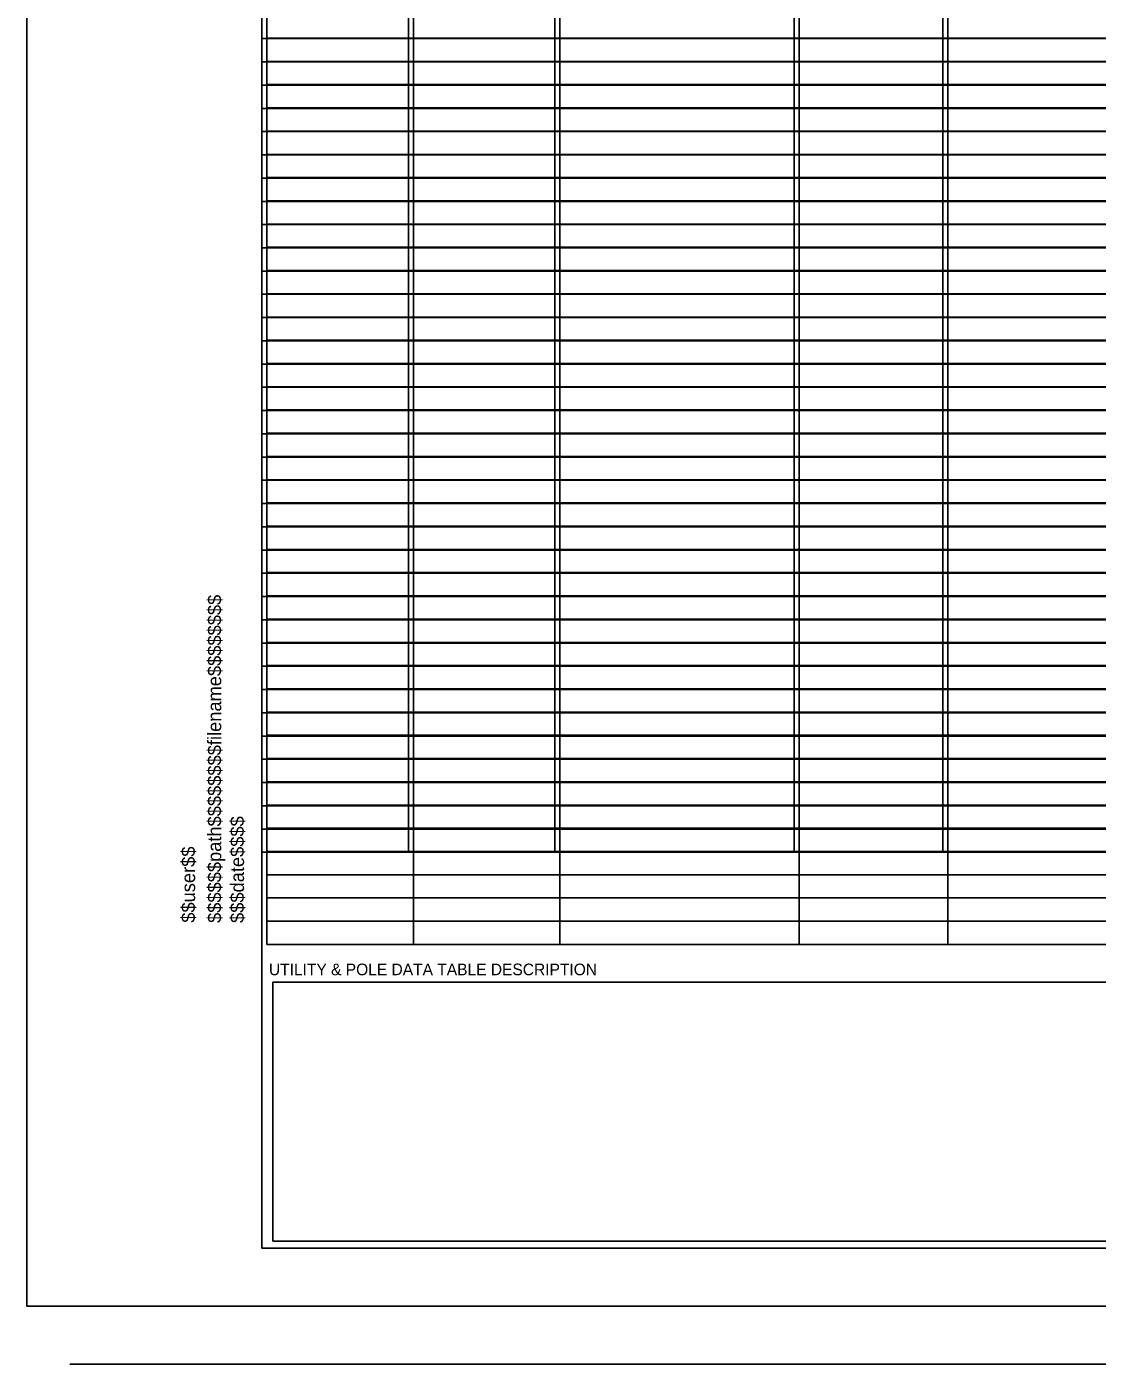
# Model space of a CAD drawing. Extents: x 11473 to 13269, y 16929 to 18079.
# Drawn here: x 11473 to 11933, y 16929 to 17505 of the extents above; entities that cross this region are included whole.
import ezdxf

# ---------------------------------------------------------------- set-up
doc = ezdxf.new("R2010")
doc.units = 0
for name, color, linetype in [('RD_SHT_Bndy', 7, 'Continuous'), ('RD_SHT_ID', 7, 'Continuous'), ('RD_SHT_Iplotshp', 7, 'Continuous'), ('RD_SHT_Misc2', 7, 'Continuous'), ('RD_SHT_Snap', 7, 'Continuous'), ('RD_SHT_TX', 7, 'Continuous')]:
    doc.layers.add(name, color=color, linetype=linetype)

msp = doc.modelspace()

# ---------------------------------------------------------------- linework, layer by layer
at = {"layer": 'RD_SHT_Bndy'}
for p, q in [((11573.83, 18029.35), (11573.83, 16979.35)), ((11573.83, 17129.35), (11573.83, 16979.4)), ((11573.83, 16979.35), (13248.83, 16979.35)), ((13251.23, 16954.35), (11491.23, 16954.35)), ((13251.23, 16929.35), (11491.23, 16929.35))]:
    msp.add_line(p, q, dxfattribs=at)
for points in [[(11573.83, 17499.8), (11636.83, 17499.8), (11636.83, 17509.81), (11573.83, 17509.81)], [(11636.83, 17499.8), (11699.83, 17499.8), (11699.83, 17509.81), (11636.83, 17509.81)], [(11699.83, 17499.8), (11802.84, 17499.8), (11802.84, 17509.81), (11699.83, 17509.81)], [(11802.84, 17499.8), (11866.84, 17499.8), (11866.84, 17509.81), (11802.84, 17509.81)], [(11866.84, 17499.8), (11973.81, 17499.8), (11973.81, 17509.81), (11866.84, 17509.81)], [(11573.83, 17489.8), (11636.83, 17489.8), (11636.83, 17499.8), (11573.83, 17499.8)], [(11636.83, 17489.8), (11699.83, 17489.8), (11699.83, 17499.8), (11636.83, 17499.8)], [(11699.83, 17489.8), (11802.84, 17489.8), (11802.84, 17499.8), (11699.83, 17499.8)], [(11802.84, 17489.8), (11866.84, 17489.8), (11866.84, 17499.8), (11802.84, 17499.8)], [(11866.84, 17489.8), (11973.81, 17489.8), (11973.81, 17499.8), (11866.84, 17499.8)], [(11573.83, 17479.8), (11636.83, 17479.8), (11636.83, 17489.8), (11573.83, 17489.8)], [(11636.83, 17479.8), (11699.83, 17479.8), (11699.83, 17489.8), (11636.83, 17489.8)], [(11699.83, 17479.8), (11802.84, 17479.8), (11802.84, 17489.8), (11699.83, 17489.8)], [(11802.84, 17479.8), (11866.84, 17479.8), (11866.84, 17489.8), (11802.84, 17489.8)], [(11866.84, 17479.8), (11973.81, 17479.8), (11973.81, 17489.8), (11866.84, 17489.8)], [(11573.83, 17469.79), (11636.83, 17469.79), (11636.83, 17479.8), (11573.83, 17479.8)], [(11636.83, 17469.79), (11699.83, 17469.79), (11699.83, 17479.8), (11636.83, 17479.8)], [(11699.83, 17469.79), (11802.84, 17469.79), (11802.84, 17479.8), (11699.83, 17479.8)], [(11802.84, 17469.79), (11866.84, 17469.79), (11866.84, 17479.8), (11802.84, 17479.8)], [(11866.84, 17469.79), (11973.81, 17469.79), (11973.81, 17479.8), (11866.84, 17479.8)], [(11573.83, 17459.79), (11636.83, 17459.79), (11636.83, 17469.79), (11573.83, 17469.79)], [(11636.83, 17459.79), (11699.83, 17459.79), (11699.83, 17469.79), (11636.83, 17469.79)], [(11699.83, 17459.79), (11802.84, 17459.79), (11802.84, 17469.79), (11699.83, 17469.79)], [(11802.84, 17459.79), (11866.84, 17459.79), (11866.84, 17469.79), (11802.84, 17469.79)], [(11866.84, 17459.79), (11973.81, 17459.79), (11973.81, 17469.79), (11866.84, 17469.79)], [(11573.83, 17449.78), (11636.83, 17449.78), (11636.83, 17459.79), (11573.83, 17459.79)], [(11636.83, 17449.78), (11699.83, 17449.78), (11699.83, 17459.79), (11636.83, 17459.79)], [(11699.83, 17449.78), (11802.84, 17449.78), (11802.84, 17459.79), (11699.83, 17459.79)], [(11802.84, 17449.78), (11866.84, 17449.78), (11866.84, 17459.79), (11802.84, 17459.79)], [(11866.84, 17449.78), (11973.81, 17449.78), (11973.81, 17459.79), (11866.84, 17459.79)], [(11573.83, 17439.78), (11636.83, 17439.78), (11636.83, 17449.78), (11573.83, 17449.78)], [(11636.83, 17439.78), (11699.83, 17439.78), (11699.83, 17449.78), (11636.83, 17449.78)], [(11699.83, 17439.78), (11802.84, 17439.78), (11802.84, 17449.78), (11699.83, 17449.78)], [(11802.84, 17439.78), (11866.84, 17439.78), (11866.84, 17449.78), (11802.84, 17449.78)], [(11866.84, 17439.78), (11973.81, 17439.78), (11973.81, 17449.78), (11866.84, 17449.78)], [(11573.83, 17429.77), (11636.83, 17429.77), (11636.83, 17439.78), (11573.83, 17439.78)], [(11636.83, 17429.77), (11699.83, 17429.77), (11699.83, 17439.78), (11636.83, 17439.78)], [(11699.83, 17429.77), (11802.84, 17429.77), (11802.84, 17439.78), (11699.83, 17439.78)], [(11802.84, 17429.77), (11866.84, 17429.77), (11866.84, 17439.78), (11802.84, 17439.78)], [(11866.84, 17429.77), (11973.81, 17429.77), (11973.81, 17439.78), (11866.84, 17439.78)], [(11573.83, 17419.77), (11636.83, 17419.77), (11636.83, 17429.77), (11573.83, 17429.77)], [(11636.83, 17419.77), (11699.83, 17419.77), (11699.83, 17429.77), (11636.83, 17429.77)], [(11699.83, 17419.77), (11802.84, 17419.77), (11802.84, 17429.77), (11699.83, 17429.77)], [(11802.84, 17419.77), (11866.84, 17419.77), (11866.84, 17429.77), (11802.84, 17429.77)], [(11866.84, 17419.77), (11973.81, 17419.77), (11973.81, 17429.77), (11866.84, 17429.77)], [(11573.83, 17409.77), (11636.83, 17409.77), (11636.83, 17419.77), (11573.83, 17419.77)], [(11636.83, 17409.77), (11699.83, 17409.77), (11699.83, 17419.77), (11636.83, 17419.77)], [(11699.83, 17409.77), (11802.84, 17409.77), (11802.84, 17419.77), (11699.83, 17419.77)], [(11802.84, 17409.77), (11866.84, 17409.77), (11866.84, 17419.77), (11802.84, 17419.77)], [(11866.84, 17409.77), (11973.81, 17409.77), (11973.81, 17419.77), (11866.84, 17419.77)], [(11573.83, 17399.76), (11636.83, 17399.76), (11636.83, 17409.77), (11573.83, 17409.77)], [(11636.83, 17399.76), (11699.83, 17399.76), (11699.83, 17409.77), (11636.83, 17409.77)], [(11699.83, 17399.76), (11802.84, 17399.76), (11802.84, 17409.77), (11699.83, 17409.77)], [(11802.84, 17399.76), (11866.84, 17399.76), (11866.84, 17409.77), (11802.84, 17409.77)], [(11866.84, 17399.76), (11973.81, 17399.76), (11973.81, 17409.77), (11866.84, 17409.77)], [(11573.83, 17389.76), (11636.83, 17389.76), (11636.83, 17399.76), (11573.83, 17399.76)], [(11636.83, 17389.76), (11699.83, 17389.76), (11699.83, 17399.76), (11636.83, 17399.76)], [(11699.83, 17389.76), (11802.84, 17389.76), (11802.84, 17399.76), (11699.83, 17399.76)], [(11802.84, 17389.76), (11866.84, 17389.76), (11866.84, 17399.76), (11802.84, 17399.76)], [(11866.84, 17389.76), (11973.81, 17389.76), (11973.81, 17399.76), (11866.84, 17399.76)], [(11573.83, 17379.75), (11636.83, 17379.75), (11636.83, 17389.76), (11573.83, 17389.76)], [(11636.83, 17379.75), (11699.83, 17379.75), (11699.83, 17389.76), (11636.83, 17389.76)], [(11699.83, 17379.75), (11802.84, 17379.75), (11802.84, 17389.76), (11699.83, 17389.76)], [(11802.84, 17379.75), (11866.84, 17379.75), (11866.84, 17389.76), (11802.84, 17389.76)], [(11866.84, 17379.75), (11973.81, 17379.75), (11973.81, 17389.76), (11866.84, 17389.76)], [(11573.83, 17369.75), (11636.83, 17369.75), (11636.83, 17379.75), (11573.83, 17379.75)], [(11636.83, 17369.75), (11699.83, 17369.75), (11699.83, 17379.75), (11636.83, 17379.75)], [(11699.83, 17369.75), (11802.84, 17369.75), (11802.84, 17379.75), (11699.83, 17379.75)], [(11802.84, 17369.75), (11866.84, 17369.75), (11866.84, 17379.75), (11802.84, 17379.75)], [(11866.84, 17369.75), (11973.81, 17369.75), (11973.81, 17379.75), (11866.84, 17379.75)], [(11573.83, 17359.74), (11636.83, 17359.74), (11636.83, 17369.75), (11573.83, 17369.75)], [(11636.83, 17359.74), (11699.83, 17359.74), (11699.83, 17369.75), (11636.83, 17369.75)], [(11699.83, 17359.74), (11802.84, 17359.74), (11802.84, 17369.75), (11699.83, 17369.75)], [(11802.84, 17359.74), (11866.84, 17359.74), (11866.84, 17369.75), (11802.84, 17369.75)], [(11866.84, 17359.74), (11973.81, 17359.74), (11973.81, 17369.75), (11866.84, 17369.75)], [(11573.83, 17349.74), (11636.83, 17349.74), (11636.83, 17359.74), (11573.83, 17359.74)], [(11636.83, 17349.74), (11699.83, 17349.74), (11699.83, 17359.74), (11636.83, 17359.74)], [(11699.83, 17349.74), (11802.84, 17349.74), (11802.84, 17359.74), (11699.83, 17359.74)], [(11802.84, 17349.74), (11866.84, 17349.74), (11866.84, 17359.74), (11802.84, 17359.74)], [(11866.84, 17349.74), (11973.81, 17349.74), (11973.81, 17359.74), (11866.84, 17359.74)], [(11573.83, 17339.74), (11636.83, 17339.74), (11636.83, 17349.74), (11573.83, 17349.74)], [(11636.83, 17339.74), (11699.83, 17339.74), (11699.83, 17349.74), (11636.83, 17349.74)], [(11699.83, 17339.74), (11802.84, 17339.74), (11802.84, 17349.74), (11699.83, 17349.74)], [(11802.84, 17339.74), (11866.84, 17339.74), (11866.84, 17349.74), (11802.84, 17349.74)], [(11866.84, 17339.74), (11973.81, 17339.74), (11973.81, 17349.74), (11866.84, 17349.74)], [(11573.83, 17329.73), (11636.83, 17329.73), (11636.83, 17339.74), (11573.83, 17339.74)], [(11636.83, 17329.73), (11699.83, 17329.73), (11699.83, 17339.74), (11636.83, 17339.74)], [(11699.83, 17329.73), (11802.84, 17329.73), (11802.84, 17339.74), (11699.83, 17339.74)], [(11802.84, 17329.73), (11866.84, 17329.73), (11866.84, 17339.74), (11802.84, 17339.74)], [(11866.84, 17329.73), (11973.81, 17329.73), (11973.81, 17339.74), (11866.84, 17339.74)], [(11573.83, 17319.73), (11636.83, 17319.73), (11636.83, 17329.73), (11573.83, 17329.73)], [(11636.83, 17319.73), (11699.83, 17319.73), (11699.83, 17329.73), (11636.83, 17329.73)], [(11699.83, 17319.73), (11802.84, 17319.73), (11802.84, 17329.73), (11699.83, 17329.73)], [(11802.84, 17319.73), (11866.84, 17319.73), (11866.84, 17329.73), (11802.84, 17329.73)], [(11866.84, 17319.73), (11973.81, 17319.73), (11973.81, 17329.73), (11866.84, 17329.73)], [(11573.83, 17309.72), (11636.83, 17309.72), (11636.83, 17319.73), (11573.83, 17319.73)], [(11636.83, 17309.72), (11699.83, 17309.72), (11699.83, 17319.73), (11636.83, 17319.73)], [(11699.83, 17309.72), (11802.84, 17309.72), (11802.84, 17319.73), (11699.83, 17319.73)], [(11802.84, 17309.72), (11866.84, 17309.72), (11866.84, 17319.73), (11802.84, 17319.73)], [(11866.84, 17309.72), (11973.81, 17309.72), (11973.81, 17319.73), (11866.84, 17319.73)], [(11573.83, 17299.72), (11636.83, 17299.72), (11636.83, 17309.72), (11573.83, 17309.72)], [(11636.83, 17299.72), (11699.83, 17299.72), (11699.83, 17309.72), (11636.83, 17309.72)], [(11699.83, 17299.72), (11802.84, 17299.72), (11802.84, 17309.72), (11699.83, 17309.72)], [(11802.84, 17299.72), (11866.84, 17299.72), (11866.84, 17309.72), (11802.84, 17309.72)], [(11866.84, 17299.72), (11973.81, 17299.72), (11973.81, 17309.72), (11866.84, 17309.72)], [(11573.83, 17289.71), (11636.83, 17289.71), (11636.83, 17299.72), (11573.83, 17299.72)], [(11636.83, 17289.71), (11699.83, 17289.71), (11699.83, 17299.72), (11636.83, 17299.72)], [(11699.83, 17289.71), (11802.84, 17289.71), (11802.84, 17299.72), (11699.83, 17299.72)], [(11802.84, 17289.71), (11866.84, 17289.71), (11866.84, 17299.72), (11802.84, 17299.72)], [(11866.84, 17289.71), (11973.81, 17289.71), (11973.81, 17299.72), (11866.84, 17299.72)], [(11573.83, 17279.71), (11636.83, 17279.71), (11636.83, 17289.71), (11573.83, 17289.71)], [(11636.83, 17279.71), (11699.83, 17279.71), (11699.83, 17289.71), (11636.83, 17289.71)], [(11699.83, 17279.71), (11802.84, 17279.71), (11802.84, 17289.71), (11699.83, 17289.71)], [(11802.84, 17279.71), (11866.84, 17279.71), (11866.84, 17289.71), (11802.84, 17289.71)], [(11866.84, 17279.71), (11973.81, 17279.71), (11973.81, 17289.71), (11866.84, 17289.71)], [(11573.83, 17269.71), (11636.83, 17269.71), (11636.83, 17279.71), (11573.83, 17279.71)], [(11636.83, 17269.71), (11699.83, 17269.71), (11699.83, 17279.71), (11636.83, 17279.71)], [(11699.83, 17269.71), (11802.84, 17269.71), (11802.84, 17279.71), (11699.83, 17279.71)], [(11802.84, 17269.71), (11866.84, 17269.71), (11866.84, 17279.71), (11802.84, 17279.71)], [(11866.84, 17269.71), (11973.81, 17269.71), (11973.81, 17279.71), (11866.84, 17279.71)], [(11573.83, 17259.7), (11636.83, 17259.7), (11636.83, 17269.71), (11573.83, 17269.71)], [(11636.83, 17259.7), (11699.83, 17259.7), (11699.83, 17269.71), (11636.83, 17269.71)], [(11699.83, 17259.7), (11802.84, 17259.7), (11802.84, 17269.71), (11699.83, 17269.71)], [(11802.84, 17259.7), (11866.84, 17259.7), (11866.84, 17269.71), (11802.84, 17269.71)], [(11866.84, 17259.7), (11973.81, 17259.7), (11973.81, 17269.71), (11866.84, 17269.71)], [(11573.83, 17249.7), (11636.83, 17249.7), (11636.83, 17259.7), (11573.83, 17259.7)], [(11636.83, 17249.7), (11699.83, 17249.7), (11699.83, 17259.7), (11636.83, 17259.7)], [(11699.83, 17249.7), (11802.84, 17249.7), (11802.84, 17259.7), (11699.83, 17259.7)], [(11802.84, 17249.7), (11866.84, 17249.7), (11866.84, 17259.7), (11802.84, 17259.7)], [(11866.84, 17249.7), (11973.81, 17249.7), (11973.81, 17259.7), (11866.84, 17259.7)], [(11573.83, 17239.69), (11636.83, 17239.69), (11636.83, 17249.7), (11573.83, 17249.7)], [(11636.83, 17239.69), (11699.83, 17239.69), (11699.83, 17249.7), (11636.83, 17249.7)], [(11699.83, 17239.69), (11802.84, 17239.69), (11802.84, 17249.7), (11699.83, 17249.7)], [(11802.84, 17239.69), (11866.84, 17239.69), (11866.84, 17249.7), (11802.84, 17249.7)], [(11866.84, 17239.69), (11973.81, 17239.69), (11973.81, 17249.7), (11866.84, 17249.7)], [(11573.83, 17229.69), (11636.83, 17229.69), (11636.83, 17239.69), (11573.83, 17239.69)], [(11636.83, 17229.69), (11699.83, 17229.69), (11699.83, 17239.69), (11636.83, 17239.69)], [(11699.83, 17229.69), (11802.84, 17229.69), (11802.84, 17239.69), (11699.83, 17239.69)], [(11802.84, 17229.69), (11866.84, 17229.69), (11866.84, 17239.69), (11802.84, 17239.69)], [(11866.84, 17229.69), (11973.81, 17229.69), (11973.81, 17239.69), (11866.84, 17239.69)], [(11573.83, 17219.68), (11636.83, 17219.68), (11636.83, 17229.69), (11573.83, 17229.69)], [(11636.83, 17219.68), (11699.83, 17219.68), (11699.83, 17229.69), (11636.83, 17229.69)], [(11699.83, 17219.68), (11802.84, 17219.68), (11802.84, 17229.69), (11699.83, 17229.69)], [(11802.84, 17219.68), (11866.84, 17219.68), (11866.84, 17229.69), (11802.84, 17229.69)], [(11866.84, 17219.68), (11973.81, 17219.68), (11973.81, 17229.69), (11866.84, 17229.69)], [(11573.83, 17209.68), (11636.83, 17209.68), (11636.83, 17219.68), (11573.83, 17219.68)], [(11636.83, 17209.68), (11699.83, 17209.68), (11699.83, 17219.68), (11636.83, 17219.68)], [(11699.83, 17209.68), (11802.84, 17209.68), (11802.84, 17219.68), (11699.83, 17219.68)], [(11802.84, 17209.68), (11866.84, 17209.68), (11866.84, 17219.68), (11802.84, 17219.68)], [(11866.84, 17209.68), (11973.81, 17209.68), (11973.81, 17219.68), (11866.84, 17219.68)], [(11573.83, 17199.68), (11636.83, 17199.68), (11636.83, 17209.68), (11573.83, 17209.68)], [(11636.83, 17199.68), (11699.83, 17199.68), (11699.83, 17209.68), (11636.83, 17209.68)], [(11699.83, 17199.68), (11802.84, 17199.68), (11802.84, 17209.68), (11699.83, 17209.68)], [(11802.84, 17199.68), (11866.84, 17199.68), (11866.84, 17209.68), (11802.84, 17209.68)], [(11866.84, 17199.68), (11973.81, 17199.68), (11973.81, 17209.68), (11866.84, 17209.68)], [(11573.83, 17189.67), (11636.83, 17189.67), (11636.83, 17199.68), (11573.83, 17199.68)], [(11636.83, 17189.67), (11699.83, 17189.67), (11699.83, 17199.68), (11636.83, 17199.68)], [(11699.83, 17189.67), (11802.84, 17189.67), (11802.84, 17199.68), (11699.83, 17199.68)], [(11802.84, 17189.67), (11866.84, 17189.67), (11866.84, 17199.68), (11802.84, 17199.68)], [(11866.84, 17189.67), (11973.81, 17189.67), (11973.81, 17199.68), (11866.84, 17199.68)], [(11573.83, 17179.67), (11636.83, 17179.67), (11636.83, 17189.67), (11573.83, 17189.67)], [(11636.83, 17179.67), (11699.83, 17179.67), (11699.83, 17189.67), (11636.83, 17189.67)], [(11699.83, 17179.67), (11802.84, 17179.67), (11802.84, 17189.67), (11699.83, 17189.67)], [(11802.84, 17179.67), (11866.84, 17179.67), (11866.84, 17189.67), (11802.84, 17189.67)], [(11866.84, 17179.67), (11973.81, 17179.67), (11973.81, 17189.67), (11866.84, 17189.67)], [(11573.83, 17169.66), (11636.83, 17169.66), (11636.83, 17179.67), (11573.83, 17179.67)], [(11636.83, 17169.66), (11699.83, 17169.66), (11699.83, 17179.67), (11636.83, 17179.67)], [(11699.83, 17169.66), (11802.84, 17169.66), (11802.84, 17179.67), (11699.83, 17179.67)], [(11802.84, 17169.66), (11866.84, 17169.66), (11866.84, 17179.67), (11802.84, 17179.67)], [(11866.84, 17169.66), (11973.81, 17169.66), (11973.81, 17179.67), (11866.84, 17179.67)], [(11573.83, 17159.66), (11636.83, 17159.66), (11636.83, 17169.66), (11573.83, 17169.66)], [(11636.83, 17159.66), (11699.83, 17159.66), (11699.83, 17169.66), (11636.83, 17169.66)], [(11699.83, 17159.66), (11802.84, 17159.66), (11802.84, 17169.66), (11699.83, 17169.66)], [(11802.84, 17159.66), (11866.84, 17159.66), (11866.84, 17169.66), (11802.84, 17169.66)], [(11866.84, 17159.66), (11973.81, 17159.66), (11973.81, 17169.66), (11866.84, 17169.66)], [(11573.83, 17149.65), (11636.83, 17149.65), (11636.83, 17159.66), (11573.83, 17159.66)], [(11636.83, 17149.65), (11699.83, 17149.65), (11699.83, 17159.66), (11636.83, 17159.66)], [(11699.83, 17149.65), (11802.84, 17149.65), (11802.84, 17159.66), (11699.83, 17159.66)], [(11802.84, 17149.65), (11866.84, 17149.65), (11866.84, 17159.66), (11802.84, 17159.66)], [(11866.84, 17149.65), (11973.81, 17149.65), (11973.81, 17159.66), (11866.84, 17159.66)]]:
    msp.add_lwpolyline(points, close=True, dxfattribs=at)
at = {"layer": 'RD_SHT_Iplotshp'}
msp.add_lwpolyline([(11472.63, 18054.35), (13268.63, 18054.35), (13268.63, 16954.35), (11472.63, 16954.35)], close=True, dxfattribs=at)
at = {"layer": 'RD_SHT_Misc2'}
for p, q in [((11576, 17979.97), (11576, 17110)), ((11639, 17980), (11639, 17110)), ((11702, 17980), (11702, 17110)), ((11805, 17980), (11805, 17110)), ((11869.01, 17980.06), (11869.01, 17110)), ((11576, 17500), (13244, 17500)), ((11576, 17490), (13244, 17490)), ((11576, 17480), (13244, 17480)), ((11576, 17470), (13244, 17470)), ((11576, 17460), (13244, 17460)), ((11576, 17450), (13244, 17450)), ((11576, 17440), (13244, 17440)), ((11576, 17430), (13244, 17430)), ((11576, 17420), (13244, 17420)), ((11576, 17410), (13244, 17410)), ((11576, 17400), (13244, 17400)), ((11576, 17390), (13244, 17390)), ((11576, 17380), (13244, 17380)), ((11576, 17370), (13244, 17370)), ((11576, 17360), (13244, 17360)), ((11576, 17350), (13244, 17350)), ((11576, 17340), (13244, 17340)), ((11576, 17330), (13244, 17330)), ((11576, 17320), (13244, 17320)), ((11576, 17310), (13244, 17310)), ((11576, 17300), (13244, 17300)), ((11576, 17290), (13244, 17290)), ((11576, 17280), (13244, 17280)), ((11576, 17270), (13244, 17270)), ((11576, 17260), (13244, 17260)), ((11576, 17250), (13244, 17250)), ((11576, 17240), (13244, 17240)), ((11576, 17230), (13244, 17230)), ((11576, 17220), (13244, 17220)), ((11576, 17210), (13244, 17210)), ((11576, 17200), (13244, 17200)), ((11576, 17190), (13244, 17190)), ((11576, 17180), (13244, 17180)), ((11576, 17170), (13244, 17170)), ((11576, 17160), (13244, 17160)), ((11576, 17150), (13244, 17150)), ((11576, 17140), (13244, 17140)), ((11576, 17130), (13244, 17130)), ((11576, 17120), (13244, 17120)), ((11576, 17110), (13244, 17110))]:
    msp.add_line(p, q, dxfattribs=at)
at = {"layer": 'RD_SHT_Snap'}
msp.add_line((11472.63, 16954.35), (11472.63, 18054.35), dxfattribs=at)
at = {"layer": 'RD_SHT_TX'}
msp.add_lwpolyline([(11578.58, 16982.31), (12504.73, 16982.31), (12504.73, 17093.75), (11578.58, 17093.75)], close=True, dxfattribs=at)

# ---------------------------------------------------------------- texts
at = {"layer": 'RD_SHT_ID'}
for s, p in [('$$$$$$path$$$$$$$$filename$$$$$$$$', (11556.33, 17119.25)), ('$$$date$$$$', (11566.13, 17119.25)), ('$$user$$', (11545.08, 17119.35))]:
    msp.add_text(s, height=5.88, rotation=90, dxfattribs=at).set_placement(p)
at = {"layer": 'RD_SHT_TX'}
msp.add_text('UTILITY & POLE DATA TABLE DESCRIPTION', height=5, dxfattribs=at).set_placement((11576.84, 17096.75))

doc.saveas('drawing.dxf')
